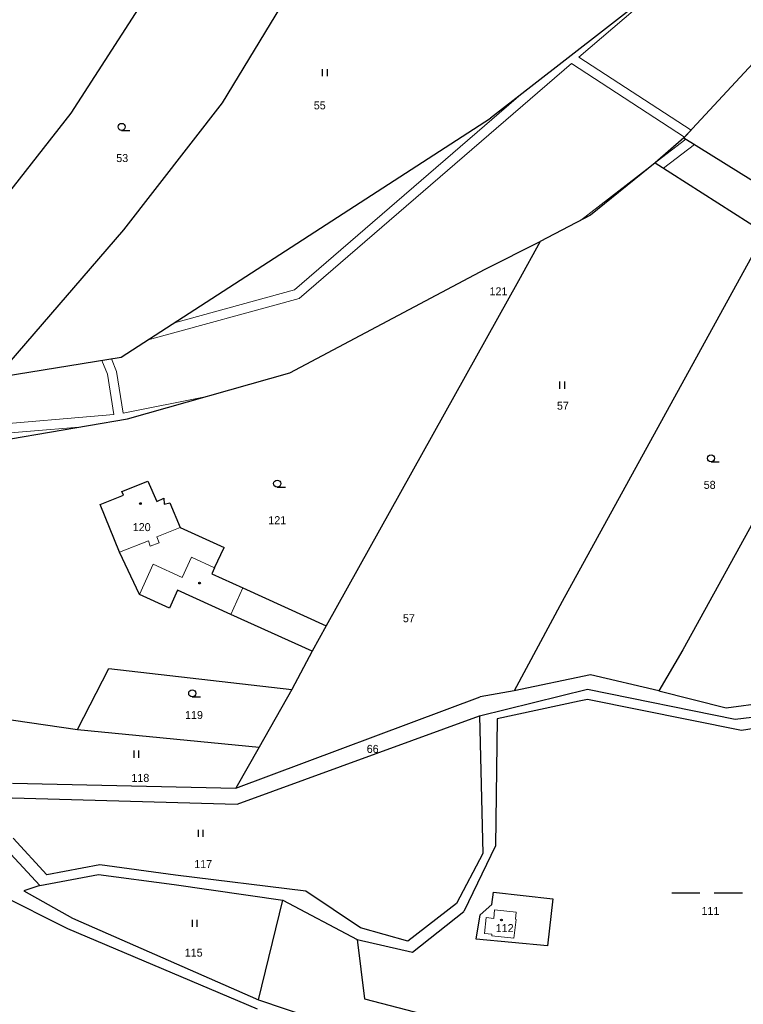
# Model space of a CAD drawing. Extents: x -727701 to -724405, y -960481 to -957284.
# Drawn here: x -726347.6 to -726194, y -958285.9 to -958076.9 of the extents above; entities that cross this region are included whole.
import ezdxf

# ---------------------------------------------------------------- set-up
doc = ezdxf.new("R2010")
doc.units = 0
doc.header["$LTSCALE"] = 0.68
for name, color, linetype, lineweight in [('1', 7, 'Continuous', 25), ('13', 7, 'Continuous', 13), ('3', 7, 'Continuous', 25), ('4', 7, 'Continuous', 13), ('5', 7, 'Continuous', 25)]:
    doc.layers.add(name, color=color, linetype=linetype, lineweight=lineweight)
doc.layers.add('2', color=7, linetype='Continuous')

msp = doc.modelspace()

# ---------------------------------------------------------------- linework, layer by layer
at = {"layer": '1'}
for p, q in [((-726308.84, -958053.35), (-726336.78, -958096.77)), ((-726279.07, -958052.32), (-726304.61, -958094.57)), ((-726202.34, -958062.52), (-726247.68, -958097.8)), ((-726183.72, -958077.25), (-726206.6, -958101.98)), ((-726304.61, -958094.57), (-726325.56, -958121.52)), ((-726336.78, -958096.77), (-726359.33, -958125.49)), ((-726326.11, -958148.57), (-726247.68, -958097.8)), ((-726206.6, -958101.98), (-726212.67, -958107.28)), ((-726206.6, -958101.98), (-726162.64, -958129.41)), ((-726212.67, -958107.28), (-726226.4, -958118.37)), ((-726212.67, -958107.28), (-726189.44, -958122.17)), ((-726226.4, -958118.37), (-726237.1, -958123.95)), ((-726325.56, -958121.52), (-726349.96, -958149.77)), ((-726189.44, -958122.17), (-726232.42, -958200.38)), ((-726248.8, -958129.85), (-726237.1, -958123.95)), ((-726237.1, -958123.95), (-726241.7, -958132.3)), ((-726290.23, -958151.88), (-726248.8, -958129.85)), ((-726241.7, -958132.3), (-726282.55, -958205.55)), ((-726165.7, -958136.02), (-726206.85, -958210.65)), ((-726350.91, -958152.58), (-726326.11, -958148.57)), ((-726324.7, -958161.6), (-726290.23, -958151.88)), ((-726349.55, -958165.85), (-726324.7, -958161.6)), ((-726325.9, -958177.05), (-726320.4, -958174.85)), ((-726320.4, -958174.85), (-726318.5, -958179.15)), ((-726330.5, -958179.8), (-726325.55, -958177.8)), ((-726325.55, -958177.8), (-726325.9, -958177.05)), ((-726318.5, -958179.15), (-726317.05, -958178.5)), ((-726317.05, -958178.5), (-726316.95, -958179.75)), ((-726326.4, -958189.95), (-726330.5, -958179.8)), ((-726316.95, -958179.75), (-726315.75, -958179.45)), ((-726315.75, -958179.45), (-726313.55, -958184.7)), ((-726313.55, -958184.7), (-726304.2, -958188.93)), ((-726306.26, -958193.26), (-726304.2, -958188.93)), ((-726322.19, -958198.92), (-726326.4, -958189.95)), ((-726306.26, -958193.26), (-726306.84, -958194.53)), ((-726306.84, -958194.53), (-726300.25, -958197.51)), ((-726300.25, -958197.51), (-726282.55, -958205.55)), ((-726315.79, -958201.81), (-726322.19, -958198.92)), ((-726314.08, -958198.03), (-726315.79, -958201.81)), ((-726302.8, -958203.14), (-726314.08, -958198.03)), ((-726232.42, -958200.38), (-726242.6, -958219.35)), ((-726285.5, -958210.95), (-726302.8, -958203.14)), ((-726282.55, -958205.55), (-726285.5, -958210.95)), ((-726285.5, -958210.95), (-726289.85, -958219.1)), ((-726206.85, -958210.65), (-726211.9, -958219.35)), ((-726335.35, -958227.55), (-726328.67, -958214.65)), ((-726328.67, -958214.65), (-726289.85, -958219.1)), ((-726226.4, -958216), (-726242.6, -958219.35)), ((-726211.9, -958219.35), (-726226.4, -958216)), ((-726289.85, -958219.1), (-726296.75, -958231.3)), ((-726250, -958224.7), (-726227.1, -958219)), ((-726242.6, -958219.35), (-726249.86, -958220.65)), ((-726227.1, -958219), (-726195.7, -958225.4)), ((-726211.9, -958219.35), (-726197.6, -958223)), ((-726301.76, -958240.07), (-726249.86, -958220.65)), ((-726228.8, -958221.6), (-726246.22, -958225.35)), ((-726227.1, -958221.2), (-726228.8, -958221.6)), ((-726194.4, -958227.8), (-726227.1, -958221.2)), ((-726197.6, -958223), (-726181.2, -958220.7)), ((-726364.62, -958223.38), (-726335.35, -958227.55)), ((-726301.43, -958243.43), (-726250, -958224.7)), ((-726250, -958224.7), (-726249.31, -958253.9)), ((-726195.7, -958225.4), (-726175, -958222.9)), ((-726246.22, -958225.35), (-726246.58, -958252.28)), ((-726335.35, -958227.55), (-726296.75, -958231.3)), ((-726189.4, -958227.05), (-726194.4, -958227.8)), ((-726296.75, -958231.3), (-726301.76, -958240.07)), ((-726349.16, -958238.96), (-726301.76, -958240.07)), ((-726349.22, -958242.08), (-726301.43, -958243.43)), ((-726341.86, -958258.44), (-726348.99, -958250.64)), ((-726350.44, -958253.08), (-726343.31, -958260.71)), ((-726249.31, -958253.9), (-726254.88, -958264.54)), ((-726246.58, -958252.28), (-726253.34, -958266.24)), ((-726330.59, -958256.34), (-726341.86, -958258.44)), ((-726314.54, -958258.54), (-726330.59, -958256.34)), ((-726343.31, -958260.71), (-726330.88, -958258.38)), ((-726330.88, -958258.38), (-726314.82, -958260.52)), ((-726286.85, -958261.91), (-726314.54, -958258.54)), ((-726343.31, -958260.71), (-726346.77, -958261.82)), ((-726346.77, -958261.82), (-726336.4, -958267.64)), ((-726314.82, -958260.52), (-726291.78, -958263.79)), ((-726275.28, -958269.72), (-726286.85, -958261.91)), ((-726247.03, -958262.12), (-726234.43, -958263.53)), ((-726352.17, -958262.44), (-726337.5, -958269.82)), ((-726296.9, -958284.95), (-726291.78, -958263.79)), ((-726291.78, -958263.79), (-726275.99, -958272.18)), ((-726234.43, -958263.53), (-726235.58, -958273.51)), ((-726254.88, -958264.54), (-726265.2, -958272.5)), ((-726264.23, -958274.89), (-726253.34, -958266.24)), ((-726336.4, -958267.64), (-726296.9, -958284.95)), ((-726250.69, -958272.1), (-726249.88, -958266.95)), ((-726337.5, -958269.82), (-726297.2, -958286.9)), ((-726265.2, -958272.5), (-726275.28, -958269.72)), ((-726275.99, -958272.18), (-726264.23, -958274.89)), ((-726275.99, -958272.18), (-726274.4, -958284.76)), ((-726235.58, -958273.51), (-726250.69, -958272.1)), ((-726296.9, -958284.95), (-726252.3, -958300)), ((-726274.4, -958284.76), (-726260.29, -958288.41))]:
    msp.add_line(p, q, dxfattribs=at)
msp.add_lwpolyline([(-726249.88, -958266.95), (-726247.38, -958264.76), (-726247.03, -958262.12)], dxfattribs=at)
at = {"layer": '13'}
for points in [[(-726207.74, -958066.72), (-726240.63, -958092.31), (-726289.25, -958134.25), (-726314.78, -958141.24), (-726320.34, -958144.83), (-726288.29, -958136.06), (-726230.48, -958086.2), (-726206.45, -958101.82), (-726205.07, -958100.33), (-726228.9, -958084.85)], [(-726206.19, -958102.24), (-726212.26, -958106.92), (-726212.67, -958107.28), (-726210.91, -958108.41), (-726204.38, -958103.37)], [(-726212.26, -958106.92), (-726228.58, -958119.51), (-726226.4, -958118.37), (-726212.67, -958107.28)], [(-726330.19, -958149.23), (-726328.99, -958152.11), (-726327.63, -958160.74), (-726355.78, -958163.11), (-726379.48, -958163.31), (-726386.9, -958162.69), (-726412.26, -958158.49), (-726422.38, -958158.07), (-726424.3, -958159.19), (-726420.88, -958160.14), (-726412.47, -958160.48), (-726387.15, -958164.67), (-726379.56, -958165.31), (-726355.68, -958165.11), (-726335.05, -958163.37), (-726324.7, -958161.6), (-726308.26, -958156.96), (-726325.65, -958160.46), (-726327.06, -958151.56), (-726328.16, -958148.9)]]:
    msp.add_lwpolyline(points, close=True, dxfattribs=at)
at = {"layer": '3'}
for p, q in [((-726283.301, -958088.91), (-726283.301, -958087.41)), ((-726282.3, -958088.91), (-726282.3, -958087.41)), ((-726325.973, -958100.4), (-726324.223, -958100.4)), ((-726232.911, -958155.23), (-726232.911, -958153.73)), ((-726231.91, -958155.23), (-726231.91, -958153.73)), ((-726200.843, -958170.76), (-726199.093, -958170.76)), ((-726292.953, -958176.13), (-726291.203, -958176.13)), ((-726310.983, -958220.66), (-726309.233, -958220.66)), ((-726323.311, -958233.57), (-726323.311, -958232.07)), ((-726322.31, -958233.57), (-726322.31, -958232.07)), ((-726309.661, -958250.37), (-726309.661, -958248.87)), ((-726308.66, -958250.37), (-726308.66, -958248.87)), ((-726209.189, -958262.28), (-726203.189, -958262.28)), ((-726200.189, -958262.28), (-726194.189, -958262.28)), ((-726310.961, -958269.47), (-726310.961, -958267.97)), ((-726309.96, -958269.47), (-726309.96, -958267.97))]:
    msp.add_line(p, q, dxfattribs=at)
for centre in [(-726325.9729, -958099.6498), (-726200.8429, -958170.0098), (-726292.9529, -958175.3798), (-726310.9829, -958219.9098)]:
    msp.add_circle(centre, 0.75, dxfattribs=at)
at = {"layer": '4'}
for p, q in [((-726313.55, -958184.7), (-726318.5, -958186.7)), ((-726318.5, -958186.7), (-726318, -958187.95)), ((-726320.3, -958187.5), (-726326.4, -958189.95)), ((-726319.95, -958188.65), (-726320.3, -958187.5)), ((-726318, -958187.95), (-726319.95, -958188.65)), ((-726313.1, -958195.29), (-726311.17, -958191.03)), ((-726311.17, -958191.03), (-726306.26, -958193.26)), ((-726322.19, -958198.92), (-726319.28, -958192.5)), ((-726319.28, -958192.5), (-726313.1, -958195.29)), ((-726300.25, -958197.51), (-726302.8, -958203.14)), ((-726246.97, -958267.71), (-726246.78, -958265.86)), ((-726246.78, -958265.86), (-726242.2, -958266.38)), ((-726242.2, -958266.38), (-726242.37, -958267.88)), ((-726248.91, -958270.9), (-726248.57, -958267.53)), ((-726248.57, -958267.53), (-726246.97, -958267.71)), ((-726242.22, -958267.91), (-726242.71, -958271.9)), ((-726242.22, -958267.91), (-726242.37, -958267.88)), ((-726247.37, -958271.06), (-726248.91, -958270.9)), ((-726247.41, -958271.4), (-726247.37, -958271.06)), ((-726242.71, -958271.9), (-726247.41, -958271.4))]:
    msp.add_line(p, q, dxfattribs=at)
at = {"layer": '5'}
for centre in [(-726321.9868, -958179.6192), (-726309.4268, -958196.5092), (-726245.3368, -958268.0192)]:
    msp.add_circle(centre, 0.175, dxfattribs=at)

# ---------------------------------------------------------------- texts
at = {"layer": '2'}
for s, p in [('55', (-726285.18, -958095.925)), ('53', (-726327.11, -958107.115)), ('121', (-726247.87, -958135.415)), ('57', (-726233.55, -958159.685)), ('58', (-726202.39, -958176.495)), ('121', (-726294.83, -958183.995)), ('120', (-726323.61, -958185.465)), ('57', (-726266.26, -958204.805)), ('119', (-726312.51, -958225.355)), ('66', (-726273.94, -958232.555)), ('118', (-726323.9, -958238.705)), ('117', (-726310.57, -958257.015)), ('111', (-726202.86, -958266.955)), ('112', (-726246.55, -958270.595)), ('115', (-726312.57, -958275.805))]:
    msp.add_text(s, height=1.7, dxfattribs=at).set_placement(p)

doc.saveas('drawing.dxf')
